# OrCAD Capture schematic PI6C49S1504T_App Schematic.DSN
size B; title: PI6C49S1504T Application Circuit; rev: 1.0; note: Diodes Inc. Clock IC Application Engineering
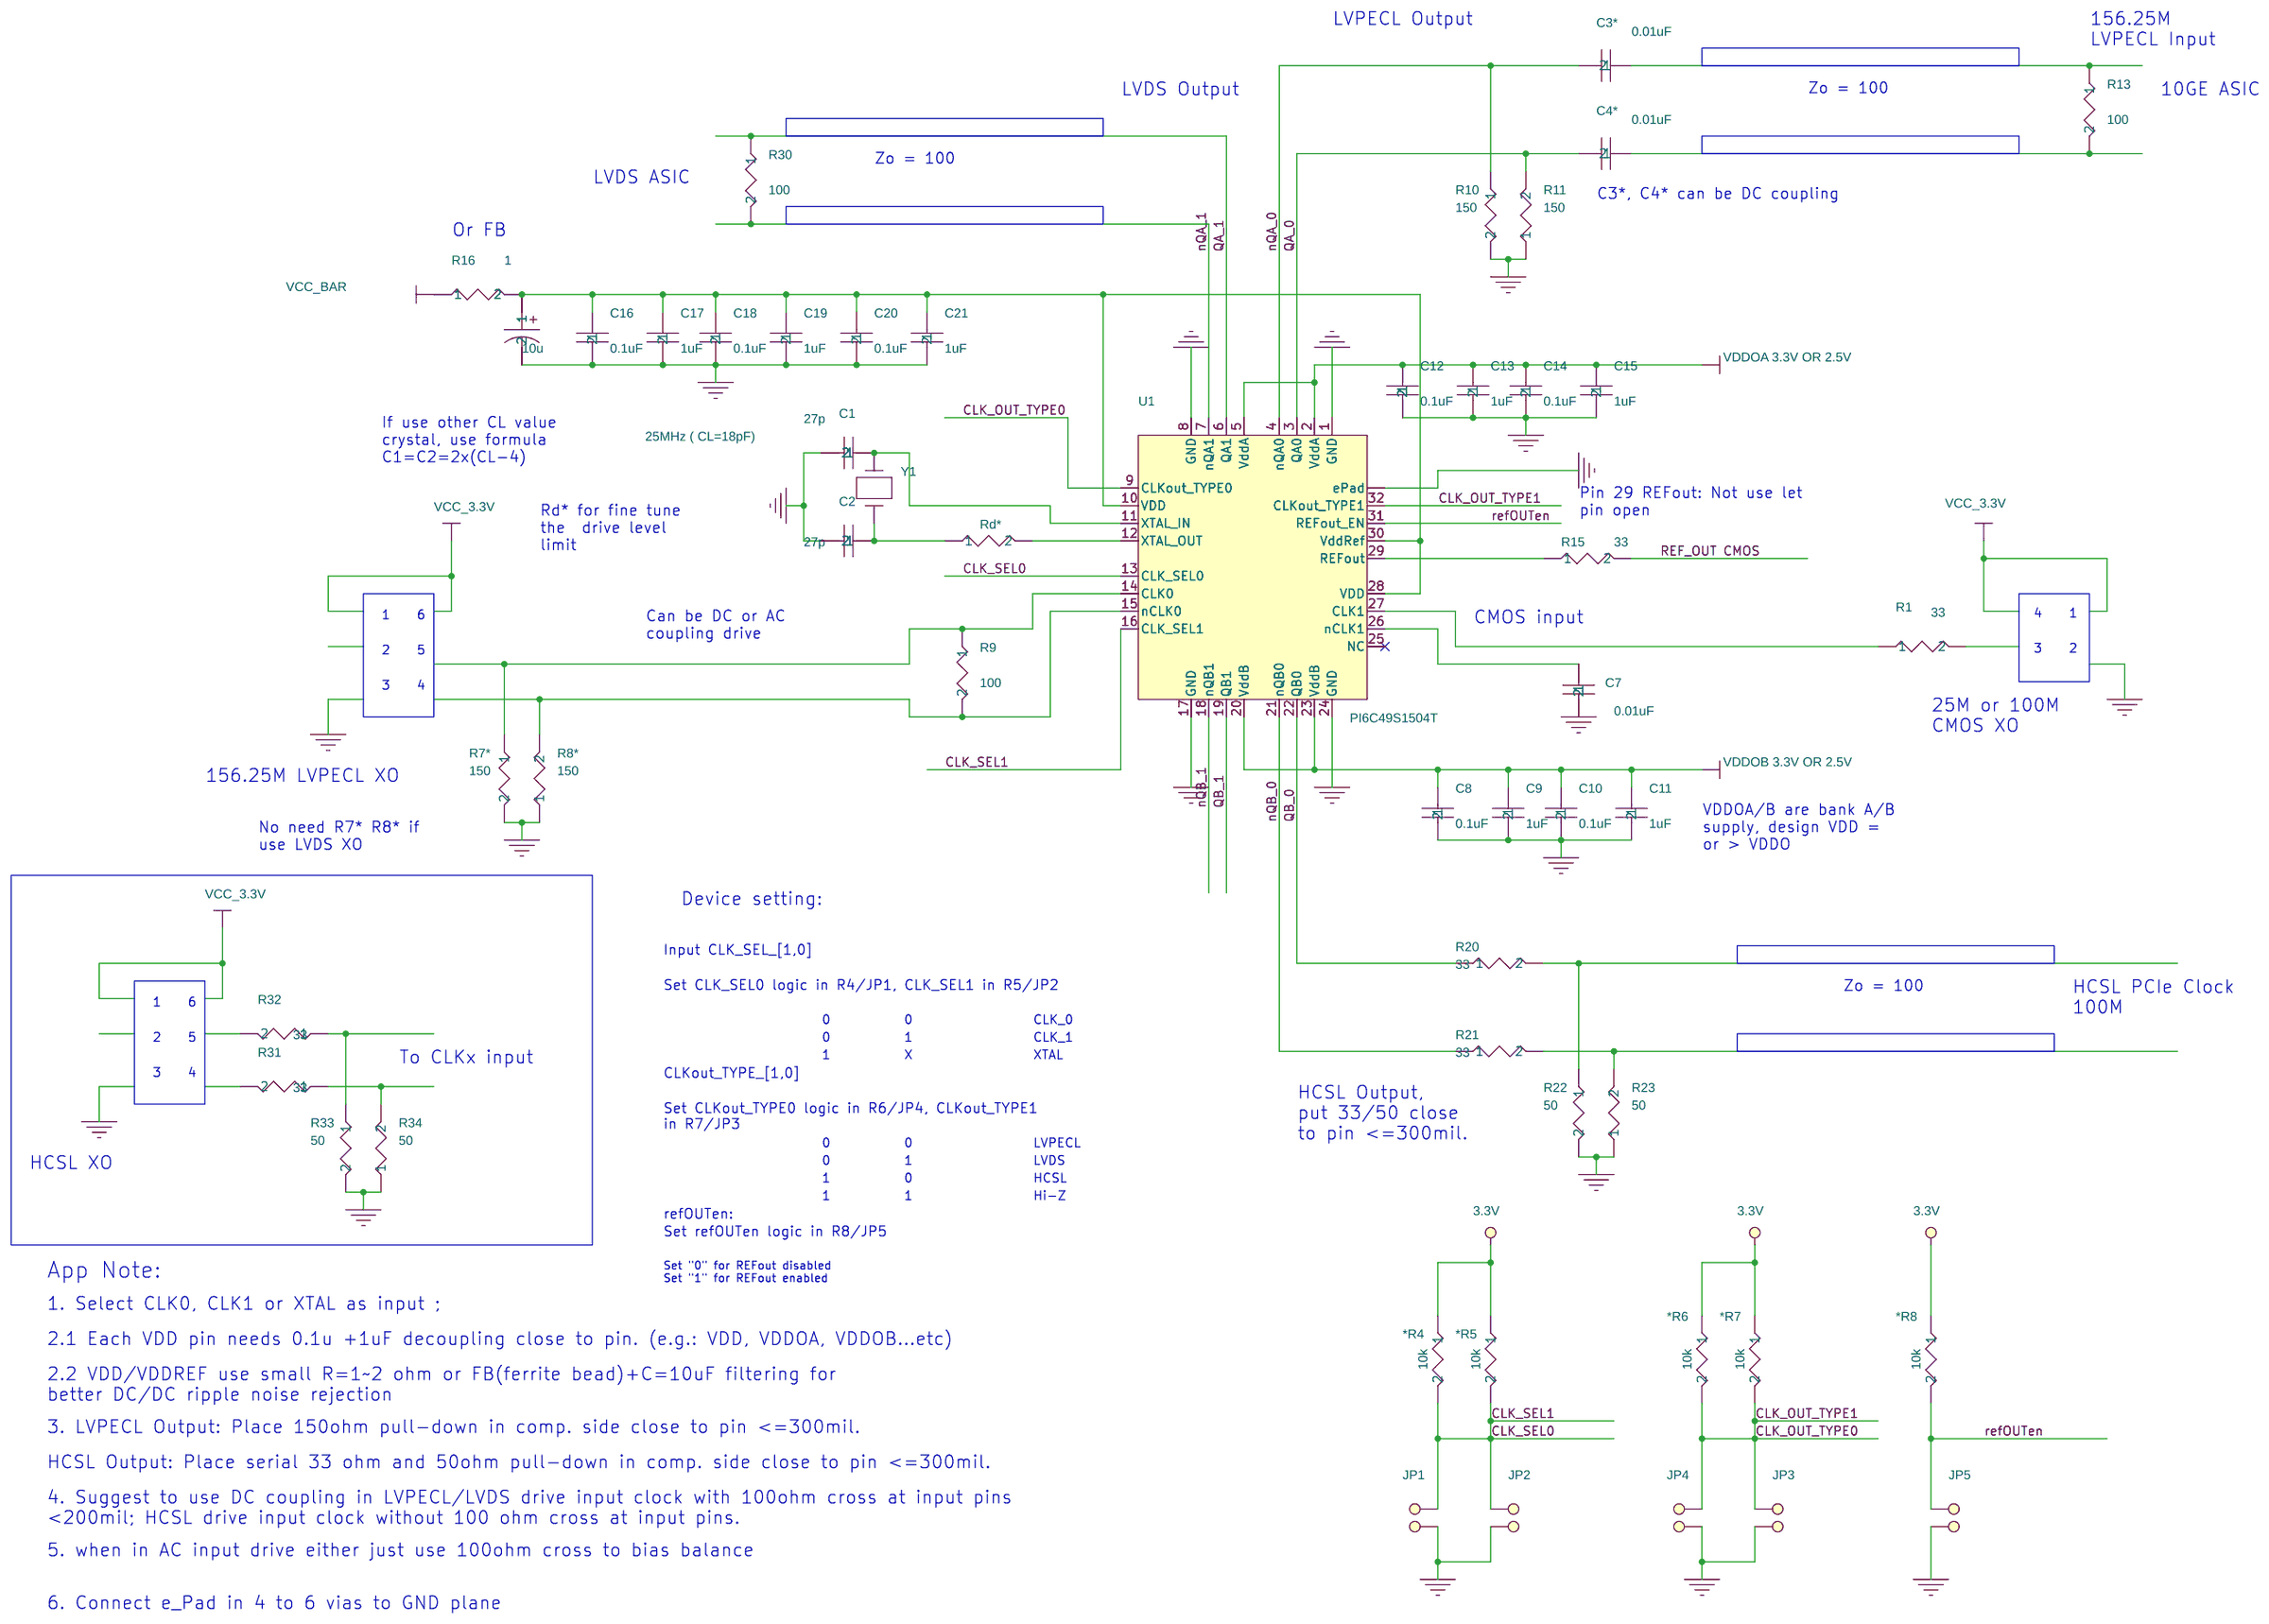
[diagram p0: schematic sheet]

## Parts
*R4  10k  [R_0402]
*R5  10k  [R_0402]
*R6  10k  [R_0402]
*R7  10k  [R_0402]
*R8  10k  [R_0402]
C1  27p  [CC_0402]
C2  27p  [CC_0402]
C3*  0.01uF  [CC_0402]
C4*  0.01uF  [CC_0402]
C7  0.01uF  [CC_0402]
C8  0.1uF  [CC_0402]
C9  1uF  [CC_0402]
C10  0.1uF  [CC_0402]
C11  1uF  [CC_0402]
C12  0.1uF  [CC_0402]
C13  1uF  [CC_0402]
C14  0.1uF  [CC_0402]
C15  1uF  [CC_0402]
C16  0.1uF  [CC_0402]
C17  1uF  [CC_0402]
C18  0.1uF  [CC_0402]
C19  1uF  [CC_0402]
C20  0.1uF  [CC_0402]
C21  1uF  [CC_0402]
EC1  10u  [CAP1000UF]
JP1  2PIN HEADER  [SIP\2P]
JP2  2PIN HEADER  [SIP\2P]
JP3  2PIN HEADER  [SIP\2P]
JP4  2PIN HEADER  [SIP\2P]
JP5  2PIN HEADER  [SIP\2P]
R1  33  [R_0402]
R7*  150  [R_0402]
R8*  150  [R_0402]
R9  100  [R_0402]
R10  150  [R_0402]
R11  150  [R_0402]
R13  100  [R_0402]
R15  33  [R_0402]
R16  1  [R_0402]
R20  33  [R_0402]
R21  33  [R_0402]
R22  50  [R_0402]
R23  50  [R_0402]
R30  100  [R_0402]
R31  33  [R_0402]
R32  33  [R_0402]
R33  50  [R_0402]
R34  50  [R_0402]
Rd*  33  [R_0402]
U1  PI6C49S1504T  [TQFN48]
Y1  25MHz ( CL=18pF)  [CRYSTAL SMD]

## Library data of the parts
*R4 = R_0402_20
*R5 = R_0402_14
*R6 = R_0402_23
*R7 = R_0402_18
*R8 = R_0402_17
C1 = C_10n_0402_5
C2 = C_10n_0402_16
C3* = C_10n_0402_4
C4* = C_10n_0402
C7 = C_10n_0402_17
C8 = C_10n_0402_2
C9 = C_10n_0402_18
C10 = C_10n_0402_9
C11 = C_10n_0402_7
C12 = C_10n_0402_14
C13 = C_10n_0402_12
C14 = C_10n_0402_8
C15 = C_10n_0402_6
C16 = C_10n_0402_15
C17 = C_10n_0402_13
C18 = C_10n_0402_11
C19 = C_10n_0402_10
C20 = C_10n_0402_3
C21 = C_10n_0402_1
EC1 = C_alum_1000u
JP1-JP5 = 2PIN_HEADER
R1 = R_0402_15
R7* = R_0402_2
R8* = R_0402_8
R9 = R_0402_1
R10 = R_0402_21
R11 = R_0402_7
R13 = R_0402_4
R15 = R_0402_5
R16 = R_0402_3
R20 = R_0402_12
R21 = R_0402_13
R22 = R_0402_16
R23 = R_0402_22
R30 = R_0402_19
R31 = R_0402_9
R32 = R_0402_11
R33 = R_0402
R34 = R_0402_10
Rd* = R_0402_6
U1 = PI6C49S1510ZDE@TQFN48_2
Y1 = Crystal_SMD

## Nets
3.3V: *R4.1 *R5.1 *R6.1 *R7.1 *R8.1
GND: C1.2 C2.2 C7.2 C8.2 C9.2 C10.2 C11.2 C12.2 C13.2 C14.2 C15.2 C16.2 C17.2 C18.2 C19.2 C20.2 C21.2 EC1.2 JP1.1 JP2.1 JP3.1 JP4.1 JP5.1 R7*.1 R8*.2 R10.1 R11.2 R22.1 R23.2 R33.1 R34.2 U1.1(GND) U1.8(GND) U1.17(GND) U1.24(GND) U1.ePad
VDD3.3V or 2.5V: R16.1
VDDOA 3.3V or 2.5V: C12.1 C13.1 C14.1 C15.1 U1.2(VddA) U1.5(VddA)
VDDOB 3.3V or 2.5V: C8.1 C9.1 C10.1 C11.1 U1.20(VddB) U1.23(VddB)
CLK_OUT_TYPE0: *R6.2 JP4.2 U1.9(CLKout_TYPE0)
CLK_OUT_TYPE1: *R7.2 JP3.2 U1.32(CLKout_TYPE1)
CLK_SEL0: *R4.2 JP1.2 U1.13(CLK_SEL0)
CLK_SEL1: *R5.2 JP2.2 U1.16(CLK_SEL1)
nQA_0: C3*.2 R11.1 U1.4(nQA0)
nQA_1: R30.2 U1.7(nQA1)
nQB_0: R21.1 U1.21(nQB0)
nQB_1: U1.18(nQB1)
QA_0: C4*.2 R10.2 U1.3(QA0)
QA_1: R30.1 U1.6(QA1)
QB_0: R20.1 U1.22(QB0)
QB_1: U1.19(QB1)
REF_OUT CMOS: R15.2
refOUTen: *R8.2 JP5.2 U1.31(REFout_EN)
N3168514: C1.1 U1.11(XTAL_IN) Y1.2
N3168602: Rd*.2 U1.12(XTAL_OUT)
N3168742: C2.1 Rd*.1 Y1.1
N3168902: R15.1 U1.29(REFout)
N3170278: R8*.1 R9.1 U1.14(CLK0)
N3171131: C3*.1 R13.1
N3171683: C4*.1 R13.2
N3173295: R20.2 R23.1
N3173303: R21.2 R22.2
N3173874: R7*.2 R9.2 U1.15(nCLK0)
N3176591: R1.1 U1.27(CLK1)
N3177547: C7.1 U1.26(nCLK1)
N3189927: C16.1 C17.1 C18.1 C19.1 C20.1 C21.1 EC1.1 R16.2 U1.10(VDD) U1.28(VDD) U1.30(VddRef)
N3686958: R32.1 R34.1
N3687022: R31.1 R33.2

Not connected (* = marked no-connect by the designer): R1 2; R31 2; R32 2; U1 25(NC)*

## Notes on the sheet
- LVPECL Output
- 156.25M
  LVPECL Input
- LVDS Output
- Zo = 100
- 10GE ASIC
- Zo = 100
- LVDS ASIC
- C3*, C4* can be DC coupling
- Or FB
- If use other CL value
  crystal, use formula
  C1=C2=2x(CL-4)
- Pin 29 REFout: Not use let
  pin open
- Rd* for fine tune
  the  drive level
  limit
- 1
- 6
- Can be DC or AC
  coupling drive
- CMOS input
- 4
- 1
- 3
- 2
- 2
- 5
- 3
- 4
- 25M or 100M
  CMOS XO
- 156.25M LVPECL XO
- VDDOA/B are bank A/B
  supply, design VDD =
  or > VDDO
- No need R7* R8* if
  use LVDS XO
- Device setting:
- Input CLK_SEL_[1,0]
- 1
- 6
- Set CLK_SEL0 logic in R4/JP1, CLK_SEL1 in R5/JP2
- Zo = 100
- HCSL PCIe Clock
  100M
- 0           0
- CLK_0
- 2
- 5
- 0           1
- CLK_1
- To CLKx input
- 1           X
- XTAL
- 3
- 4
- CLKout_TYPE_[1,0]
- HCSL Output,
  put 33/50 close
  to pin <=300mil.
- Set CLKout_TYPE0 logic in R6/JP4, CLKout_TYPE1
  in R7/JP3
- 0           0
- LVPECL
- HCSL XO
- 0           1
- LVDS
- 1           0
- HCSL
- 1           1
- Hi-Z
- refOUTen:
- Set refOUTen logic in R8/JP5
- App Note:
- Set "0" for REFout disabled
  Set "1" for REFout enabled
- 1. Select CLK0, CLK1 or XTAL as input ;
- 2.1 Each VDD pin needs 0.1u +1uF decoupling close to pin. (e.g.: VDD, VDDOA, VDDOB...etc)
- 2.2 VDD/VDDREF use small R=1~2 ohm or FB(ferrite bead)+C=10uF filtering for
  better DC/DC ripple noise rejection
- 3. LVPECL Output: Place 150ohm pull-down in comp. side close to pin <=300mil.
- HCSL Output: Place serial 33 ohm and 50ohm pull-down in comp. side close to pin <=300mil.
- 4. Suggest to use DC coupling in LVPECL/LVDS drive input clock with 100ohm cross at input pins
  <200mil; HCSL drive input clock without 100 ohm cross at input pins.
- 5. when in AC input drive either just use 100ohm cross to bias balance
- 6. Connect e_Pad in 4 to 6 vias to GND plane
